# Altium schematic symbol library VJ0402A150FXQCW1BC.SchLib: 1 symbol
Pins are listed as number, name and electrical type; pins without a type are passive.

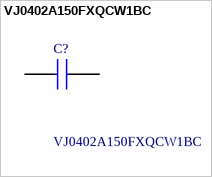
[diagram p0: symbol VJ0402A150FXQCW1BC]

## VJ0402A150FXQCW1BC
designator C?
Multilayer Ceramic Capacitors MLCC - SMD/SMT 0402 15pF 10volts C0G 1%; Manufacturer_Name: Vishay; Geometry.Height: 0.55mm
footprint CAPC1005X55N
pins: 1, 2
